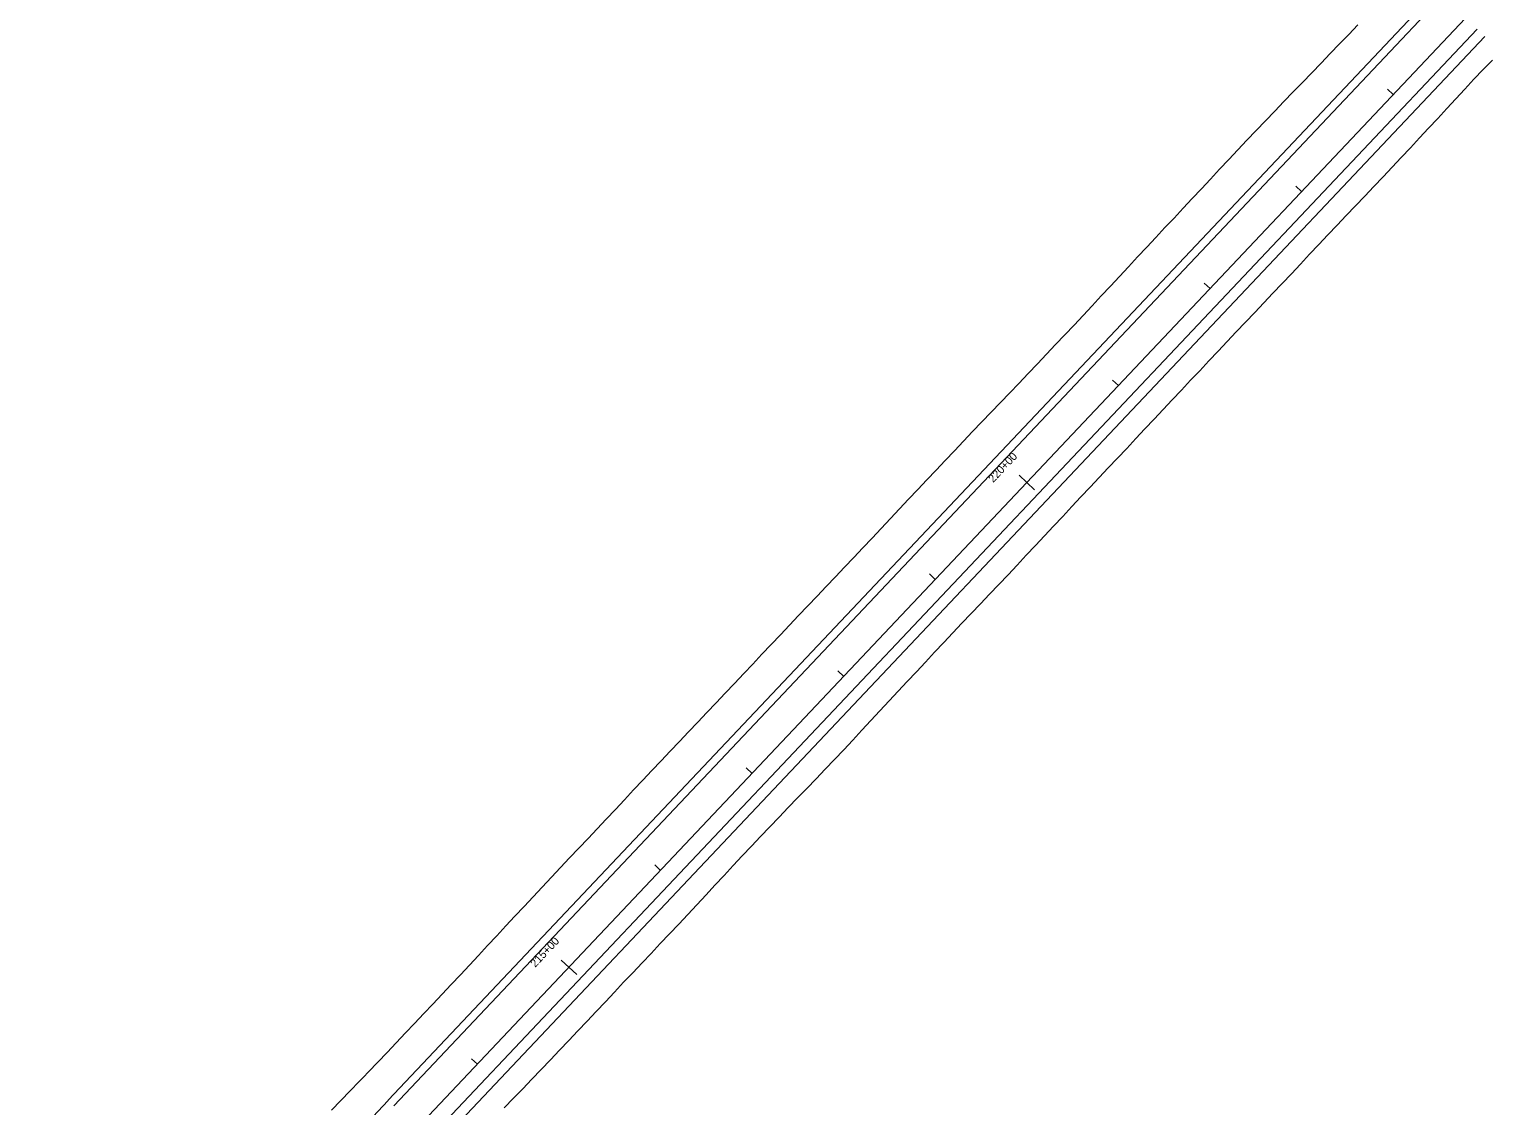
# Model space of a CAD drawing. Extents: x 1375694 to 1433473, y 1931050 to 1967991.
# Drawn here: x 1387204 to 1388295, y 1943708 to 1944515 of the extents above; entities that cross this region are included whole.
import ezdxf

# ---------------------------------------------------------------- set-up
doc = ezdxf.new("R2010")
doc.units = 0
for name, color, linetype in [('R_Horz Alg', 7, 'Continuous'), ('R_Horz Alg Annot', 7, 'Continuous'), ('R_Proposed Const Limits', 7, 'Continuous'), ('R_Proposed Road', 7, 'Continuous')]:
    doc.layers.add(name, color=color, linetype=linetype)

msp = doc.modelspace()

# ---------------------------------------------------------------- linework, layer by layer
at = {"layer": 'R_Horz Alg'}
msp.add_line((1387494.9, 1943691.7), (1388280.9, 1944523.6), dxfattribs=at)
at = {"layer": 'R_Horz Alg Annot'}
for points in [[(1388222.4, 1944470.4), (1388226.7, 1944466.3)], [(1388153.7, 1944397.7), (1388158, 1944393.6)], [(1388085, 1944325), (1388089.4, 1944320.9)], [(1388016.3, 1944252.3), (1388020.7, 1944248.2)], [(1387946.2, 1944181), (1387957.8, 1944170)], [(1387879, 1944106.9), (1387883.3, 1944102.8)], [(1387810.3, 1944034.2), (1387814.7, 1944030.1)], [(1387741.6, 1943961.6), (1387746, 1943957.4)], [(1387673, 1943888.9), (1387677.3, 1943884.7)], [(1387602.8, 1943817.5), (1387614.5, 1943806.6)], [(1387535.6, 1943743.5), (1387540, 1943739.4)]]:
    msp.add_lwpolyline(points, dxfattribs=at)
at = {"layer": 'R_Proposed Const Limits'}
for points in [[(1387430.6, 1943704.9), (1387437.6, 1943712.1), (1387444.6, 1943719.3), (1387451.5, 1943726.5), (1387454.6, 1943729.6), (1387458.5, 1943733.7), (1387465.5, 1943741), (1387472.3, 1943748.2), (1387479.2, 1943755.5), (1387486.1, 1943762.8), (1387493, 1943770), (1387499.8, 1943777.3), (1387506.7, 1943784.5), (1387513.6, 1943791.8), (1387520.5, 1943799.1), (1387527.3, 1943806.4), (1387534.1, 1943813.7), (1387540.9, 1943821), (1387547.7, 1943828.4), (1387554.5, 1943835.7), (1387561.3, 1943843), (1387568.1, 1943850.3), (1387575, 1943857.6), (1387581.8, 1943864.9), (1387588.6, 1943872.2), (1387595.5, 1943879.5), (1387602.4, 1943886.8), (1387609.2, 1943894), (1387616.1, 1943901.3), (1387623, 1943908.5), (1387629.9, 1943915.8), (1387636.7, 1943923.1), (1387643.6, 1943930.4), (1387650.4, 1943937.7), (1387657.2, 1943945), (1387664, 1943952.3), (1387670.9, 1943959.6), (1387677.8, 1943966.9), (1387684.6, 1943974.1), (1387691.5, 1943981.4), (1387698.4, 1943988.6), (1387705.3, 1943995.9), (1387712.2, 1944003.1), (1387719.1, 1944010.4), (1387725.9, 1944017.6), (1387732.8, 1944024.9), (1387739.7, 1944032.2), (1387746.6, 1944039.4), (1387753.4, 1944046.7), (1387760.3, 1944054), (1387767.2, 1944061.2), (1387774.1, 1944068.5), (1387780.9, 1944075.7), (1387787.8, 1944083), (1387794.7, 1944090.2), (1387801.6, 1944097.5), (1387808.5, 1944104.7), (1387815.4, 1944112), (1387822.3, 1944119.2), (1387829.1, 1944126.5), (1387836, 1944133.8), (1387842.8, 1944141.1), (1387849.7, 1944148.4), (1387856.5, 1944155.7), (1387863.4, 1944162.9), (1387870.2, 1944170.2), (1387877.1, 1944177.5), (1387884, 1944184.7), (1387890.8, 1944192), (1387897.7, 1944199.3), (1387904.5, 1944206.6), (1387911.4, 1944213.8), (1387918.4, 1944221), (1387925.3, 1944228.2), (1387932.3, 1944235.4), (1387939.2, 1944242.6), (1387946.1, 1944249.8), (1387953, 1944257.1), (1387959.9, 1944264.4), (1387966.8, 1944271.6), (1387973.6, 1944278.9), (1387980.5, 1944286.2), (1387987.4, 1944293.4), (1387994.2, 1944300.7), (1388001, 1944308), (1388007.8, 1944315.4), (1388014.7, 1944322.7), (1388021.5, 1944330), (1388028.3, 1944337.3), (1388035.1, 1944344.6), (1388041.9, 1944352), (1388048.7, 1944359.3), (1388055.6, 1944366.6), (1388062.4, 1944373.8), (1388069.3, 1944381.1), (1388076.1, 1944388.4), (1388083, 1944395.7), (1388089.8, 1944403), (1388096.6, 1944410.4), (1388103.4, 1944417.7), (1388110.3, 1944424.9), (1388117.1, 1944432.2), (1388124.1, 1944439.4), (1388131, 1944446.6), (1388137.9, 1944453.9), (1388144.8, 1944461.1), (1388151.8, 1944468.3), (1388158.7, 1944475.5), (1388165.6, 1944482.7), (1388172.6, 1944489.9), (1388179.5, 1944497.1), (1388186.5, 1944504.3), (1388193.4, 1944511.5), (1388200.3, 1944518.7)], [(1387560.1, 1943706.6), (1387567, 1943713.8), (1387574, 1943721), (1387580.9, 1943728.2), (1387587.9, 1943735.3), (1387594.8, 1943742.6), (1387601.7, 1943749.9), (1387608.5, 1943757.1), (1387615.4, 1943764.4), (1387622.3, 1943771.7), (1387629.1, 1943778.9), (1387636, 1943786.2), (1387642.9, 1943793.5), (1387649.7, 1943800.8), (1387656.6, 1943808), (1387663.5, 1943815.3), (1387670.4, 1943822.5), (1387677.2, 1943829.8), (1387684.1, 1943837), (1387691, 1943844.3), (1387697.9, 1943851.6), (1387704.7, 1943858.9), (1387711.5, 1943866.3), (1387718.2, 1943873.6), (1387725, 1943880.9), (1387731.8, 1943888.3), (1387738.7, 1943895.6), (1387745.5, 1943902.9), (1387752.4, 1943910.1), (1387759.3, 1943917.3), (1387766.2, 1943924.6), (1387773.1, 1943931.8), (1387780.1, 1943939), (1387787, 1943946.2), (1387794, 1943953.4), (1387800.9, 1943960.6), (1387807.8, 1943967.8), (1387814.7, 1943975.1), (1387821.5, 1943982.4), (1387828.3, 1943989.7), (1387835.1, 1943997.1), (1387841.9, 1944004.4), (1387848.7, 1944011.7), (1387855.5, 1944019), (1387862.4, 1944026.3), (1387869.2, 1944033.6), (1387876, 1944040.9), (1387882.8, 1944048.3), (1387889.7, 1944055.5), (1387896.6, 1944062.8), (1387903.4, 1944070.1), (1387910.3, 1944077.4), (1387917.2, 1944084.6), (1387924.1, 1944091.8), (1387931, 1944099), (1387938, 1944106.2), (1387944.8, 1944113.5), (1387951.6, 1944120.9), (1387958.4, 1944128.2), (1387965.2, 1944135.6), (1387972.1, 1944142.8), (1387978.9, 1944150.1), (1387985.7, 1944157.5), (1387992.5, 1944164.8), (1387999.4, 1944172.1), (1388006.3, 1944179.3), (1388013.1, 1944186.6), (1388020, 1944193.8), (1388026.9, 1944201.1), (1388033.7, 1944208.4), (1388040.6, 1944215.7), (1388047.4, 1944223), (1388054.3, 1944230.2), (1388061.1, 1944237.5), (1388068, 1944244.8), (1388074.8, 1944252.1), (1388081.7, 1944259.3), (1388088.6, 1944266.6), (1388095.4, 1944273.9), (1388102.3, 1944281.2), (1388109.1, 1944288.5), (1388116, 1944295.7), (1388122.9, 1944303), (1388129.7, 1944310.3), (1388136.6, 1944317.5), (1388143.5, 1944324.8), (1388150.4, 1944332), (1388157.2, 1944339.3), (1388164, 1944346.6), (1388170.9, 1944353.9), (1388177.8, 1944361.2), (1388184.6, 1944368.5), (1388191.5, 1944375.7), (1388198.4, 1944382.9), (1388205.4, 1944390.1), (1388212.3, 1944397.4), (1388219.2, 1944404.6), (1388226, 1944411.9), (1388232.8, 1944419.2), (1388239.7, 1944426.5), (1388246.5, 1944433.8), (1388253.3, 1944441.2), (1388260.1, 1944448.5), (1388266.9, 1944455.8), (1388273.7, 1944463.2), (1388280.5, 1944470.5), (1388287.3, 1944477.8), (1388294.1, 1944485.2), (1388301.2, 1944492.2)]]:
    msp.add_lwpolyline(points, dxfattribs=at)
at = {"layer": 'R_Proposed Road'}
for p, q in [((1387473.1, 1943712.3), (1388259.1, 1944544.2)), ((1387477.5, 1943708.2), (1388263.5, 1944540.1)), ((1387503.6, 1943683.4), (1388289.6, 1944515.4)), ((1387509.4, 1943677.9), (1388295.5, 1944509.9)), ((1387203.9, 1943426.3), (1387473.1, 1943712.2))]:
    msp.add_line(p, q, dxfattribs=at)

# ---------------------------------------------------------------- texts
at = {"layer": 'R_Horz Alg Annot'}
for s, p in [('220+00', (1387926.8, 1944175)), ('215+00', (1387583.4, 1943811.6))]:
    msp.add_text(s, height=6, rotation=46.6272, dxfattribs=at).set_placement(p)

doc.saveas('drawing.dxf')
